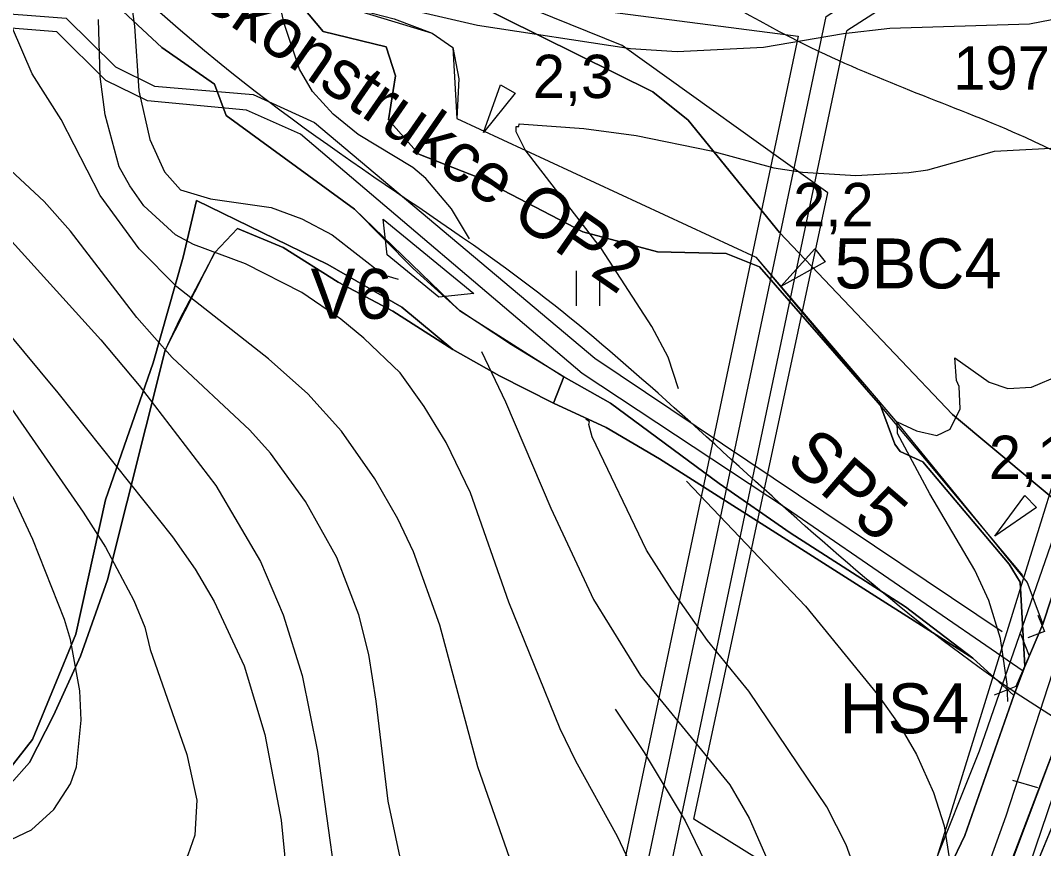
# Model space of a CAD drawing. Extents: x -684583 to -680383, y -1157874 to -1154904.
# Drawn here: x -683060.3 to -682753.2, y -1156107.3 to -1155858.8 of the extents above; entities that cross this region are included whole.
import ezdxf

# ---------------------------------------------------------------- set-up
doc = ezdxf.new("R2010")
doc.units = 0
for name, color, linetype in [('01_DOPRAVA', 7, 'Continuous'), ('01_PRVKY PSZ', 7, 'Continuous'), ('01_VRSTEVNICE', 7, 'Continuous'), ('02_KULTURY STAV', 7, 'Continuous'), ('03_PC_OBJEKTY_NÁVRH', 7, 'Continuous'), ('03_PC_OBJEKTY_STAV', 7, 'Continuous'), ('03_PC_STAV', 7, 'Continuous'), ('05_VHO_MELIORACE', 7, 'Continuous'), ('05_VHO_V_TOK', 7, 'Continuous'), ('06_BIOGEOGRAFIE', 7, 'Continuous'), ('06_ÚSES_IP', 7, 'Continuous'), ('07_ELEKTRO', 7, 'Continuous'), ('07_OCH_P A POPISY TI', 7, 'Continuous')]:
    doc.layers.add(name, color=color, linetype=linetype)

msp = doc.modelspace()

# ---------------------------------------------------------------- linework, layer by layer
at = {"layer": '01_DOPRAVA'}
msp.add_lwpolyline([(-682444.78, -1155001.44), (-682484.97, -1155081.41), (-682523.81, -1155212.27), (-682554.69, -1155333.36), (-682575.58, -1155465.36), (-682603.29, -1155587.36), (-682620.55, -1155650.97), (-682668.34, -1155796.22), (-682702.3, -1155906.34), (-682764.53, -1156097.63), (-682782.62, -1156147.93)], dxfattribs=at)
at = {"layer": '01_PRVKY PSZ'}
msp.add_lwpolyline([(-683103.66, -1155814.17), (-683023.93, -1155838.49), (-683005.49, -1155838.49), (-682978.82, -1155845.67), (-682966.79, -1155853.54), (-682936.74, -1155862.58), (-682930.53, -1155866.91), (-682929.33, -1155888.26), (-682839.59, -1155929.84), (-682759.46, -1156025.37)], dxfattribs=at)
at = {"layer": '01_VRSTEVNICE'}
for points in [[(-683028.81, -1155841.14), (-683026.1, -1155860.54), (-683024.81, -1155879.94), (-683021.53, -1155894.49), (-683017.11, -1155904.19), (-683012.26, -1155909.61), (-683003.28, -1155912.32), (-682985.02, -1155914.88), (-682975.89, -1155918.31), (-682966.76, -1155923.16), (-682951.35, -1155935.14), (-682946.93, -1155936.42)], [(-682925.53, -1155924.3), (-682930.95, -1155915.31), (-682938.66, -1155906.18), (-682942.51, -1155902.9), (-682958.91, -1155893.06), (-682966.47, -1155886.93), (-682972.61, -1155880.08), (-682976.6, -1155873.38), (-682981.17, -1155859.68), (-682982.45, -1155853.97), (-682981.88, -1155849.7), (-682977.03, -1155849.12), (-682969.04, -1155849.55), (-682923.11, -1155860.25), (-682877.18, -1155867.24), (-682863.2, -1155868.1), (-682837.24, -1155866.81), (-682813.27, -1155862.68), (-682799.29, -1155861.11), (-682757.36, -1155859.82), (-682741.38, -1155856.68)], [(-682903.85, -1156137.55), (-682922.97, -1156082.78), (-682934.38, -1156040.27), (-682942.37, -1156018.3), (-682947.07, -1156008.32), (-682953.92, -1155996.33), (-682963.91, -1155982.07), (-682974.03, -1155970.8), (-682985.87, -1155960.39), (-683013.4, -1155938.71), (-683024.67, -1155927.29), (-683036.37, -1155911.32), (-683048.07, -1155888.49), (-683056.77, -1155874.8), (-683062.76, -1155861.11)], [(-682864.48, -1156138.69), (-682881.03, -1156103.74), (-682893.58, -1156081.06), (-682898.29, -1156071.36), (-682913.69, -1156033.42), (-682925.25, -1156000.61), (-682932.52, -1155985.49), (-682939.08, -1155974.65), (-682946.36, -1155964.52), (-682957.2, -1155954.11), (-682964.19, -1155948.4), (-682975.89, -1155940.42), (-682992.72, -1155931.86), (-683008.41, -1155926.01), (-683013.83, -1155923.16), (-683023.24, -1155914.46), (-683027.52, -1155908.46), (-683030.66, -1155902.76), (-683034.94, -1155887.07), (-683036.37, -1155875.66), (-683036.94, -1155858.54)], [(-682862.77, -1155969.37), (-682865.91, -1155959.82), (-682870.76, -1155950.69), (-682885.88, -1155927.29), (-682908.84, -1155897.62), (-682911.55, -1155892.2), (-682911.55, -1155890.63), (-682910.7, -1155890.63), (-682910.56, -1155889.78), (-682891.16, -1155891.21), (-682875.47, -1155893.34), (-682852.93, -1155897.91), (-682834.1, -1155903.04), (-682825.54, -1155904.33), (-682809.56, -1155905.33), (-682793.59, -1155904.47), (-682787.88, -1155903.61), (-682767.91, -1155898.05), (-682739.67, -1155896.48), (-682729.97, -1155893.06), (-682722.12, -1155888.64), (-682713.42, -1155881.5), (-682708.82, -1155876.58), (-682703.58, -1155868.67)], [(-682946.36, -1156110.02), (-682949.93, -1156093.05), (-682953.49, -1156063.09), (-682955.77, -1156049.11), (-682958.77, -1156037.13), (-682965.33, -1156020.01), (-682974.75, -1156003.18), (-682985.3, -1155988.63), (-682991.43, -1155981.78), (-683014.83, -1155959.96), (-683025.38, -1155947.98), (-683045.35, -1155922.02), (-683053.2, -1155913.17), (-683076.45, -1155891.63)], [(-683067.75, -1155919.88), (-683036.22, -1155954.68), (-683024.67, -1155968.38), (-683001.7, -1155998.33), (-682988.3, -1156021.15), (-682981.45, -1156037.13), (-682975.74, -1156055.39), (-682971.18, -1156078.21), (-682965.76, -1156117.01), (-682963.33, -1156139.83), (-682962.76, -1156160.37), (-682964.05, -1156167.22), (-682966.47, -1156174.5), (-682969.33, -1156179.06), (-682973.03, -1156182.91), (-682977.17, -1156185.76), (-682981.45, -1156187.76), (-682991.58, -1156189.47), (-683046.07, -1156188.19), (-683064.04, -1156186.33)], [(-683080.59, -1155932.71), (-683049.06, -1155970.51), (-683014.69, -1156013.74), (-683007.84, -1156023.44), (-683002.13, -1156033.14), (-682993.15, -1156052.53), (-682987.01, -1156073.08), (-682982.02, -1156098.75), (-682981.02, -1156109.02), (-682981.45, -1156119.29), (-682983.16, -1156128.99), (-682984.87, -1156133.84), (-682987.58, -1156138.69), (-682999.28, -1156149.68), (-683012.97, -1156155.95), (-683024.1, -1156157.52), (-683035.23, -1156157.09), (-683066.89, -1156151.24)], [(-682763.92, -1156063.23), (-682764.06, -1156057.96), (-682766.06, -1156044.26), (-682769.62, -1156032.85), (-682773.76, -1156023.72), (-682787.31, -1156000.9), (-682797.01, -1155982.78), (-682797.15, -1155979.22), (-682791.31, -1155981.93), (-682785.17, -1155983.35), (-682781.18, -1155981.5), (-682778.18, -1155975.36), (-682778.47, -1155968.66), (-682779.32, -1155966.81), (-682779.85, -1155960.09), (-682769.48, -1155967.38), (-682763.92, -1155969.23), (-682756.79, -1155968.8), (-682748.23, -1155965.24), (-682741.09, -1155960.1), (-682731.82, -1155949.97), (-682724.12, -1155937.85), (-682722.55, -1155934.28)], [(-683077.45, -1155954.68), (-683041.5, -1156006.32), (-683034.8, -1156016.87), (-683026.24, -1156032.85), (-683022.96, -1156040.84), (-683021.39, -1156047.54), (-683010.41, -1156079.07), (-683007.41, -1156092.76), (-683007.98, -1156103.32), (-683010.12, -1156109.31), (-683015.26, -1156116.3), (-683018.68, -1156119.15), (-683030.66, -1156126.14), (-683042.65, -1156129.99), (-683054.63, -1156131.42), (-683087.43, -1156132.7)], [(-682921.93, -1155958.14), (-682914.69, -1155973.22), (-682901.14, -1156005.18), (-682888.3, -1156032.56), (-682874.18, -1156055.39), (-682847.36, -1156088.2), (-682841.52, -1156098.18), (-682835.53, -1156111.88)], [(-682808.28, -1156117.58), (-682812.42, -1156106.17), (-682818.27, -1156094.76), (-682841.66, -1156060.09), (-682854.07, -1156044.83), (-682864.77, -1156029.71), (-682872.33, -1156017.73), (-682888.73, -1155983.78), (-682889.73, -1155980.07), (-682889.45, -1155979.22), (-682890.59, -1155978.5)], [(-683065.18, -1156105.6), (-683057.05, -1156101.75), (-683050.35, -1156095.61), (-683045.35, -1156087.91), (-683043.5, -1156082.78), (-683042.07, -1156068.8), (-683042.5, -1156059.95), (-683045.35, -1156044.55), (-683047.07, -1156038.56), (-683056.62, -1156014.59), (-683064.04, -1155998.62)], [(-682860.35, -1155997.05), (-682824.68, -1156034.56), (-682803, -1156061.09), (-682796.3, -1156070.51), (-682791.31, -1156079.07), (-682786.17, -1156090.48), (-682783.03, -1156100.46), (-682781.32, -1156111.45)], [(-682881.82, -1156065.53), (-682873.04, -1156078.5), (-682860.77, -1156099.04), (-682854.78, -1156111.45), (-682849.5, -1156125.85), (-682847.08, -1156134.98), (-682844.23, -1156151.53), (-682837.38, -1156204.02), (-682836.95, -1156222.28), (-682839.66, -1156245.39), (-682843.66, -1156261.37), (-682847.36, -1156272.78), (-682851.36, -1156281.91), (-682859.06, -1156295.03), (-682870.76, -1156308.01)], [(-682754.93, -1156089.05), (-682762.35, -1156086.91)]]:
    msp.add_lwpolyline(points, dxfattribs=at)
at = {"layer": '02_KULTURY STAV'}
for points in [[(-682742.95, -1156008.33), (-682780.55, -1155977.07), (-682832.46, -1155922.39), (-682859.9, -1155888.72), (-682870.47, -1155880.23), (-682937.94, -1155846.74), (-682971.26, -1155836.19), (-683011.54, -1155826.68), (-683018.47, -1155820.23), (-683023.17, -1155813.67), (-683027.63, -1155799.73), (-683026.39, -1155782.8), (-683015.08, -1155760.81), (-683000.24, -1155747.04), (-682981.15, -1155735.79), (-682979.06, -1155725.2), (-682969.44, -1155700.39)], [(-682982.05, -1155846.95), (-682969.48, -1155862.12), (-682950.5, -1155866.7), (-682947.78, -1155875.42), (-682949.83, -1155888.58), (-682940.72, -1155898.9), (-682922.63, -1155905.99), (-682891.46, -1155922.2), (-682869.06, -1155928.21), (-682848.46, -1155928.75), (-682838.47, -1155932.76), (-682802.16, -1155974.34), (-682797.79, -1155985.99), (-682796.23, -1155988.19), (-682789.4, -1155991.25), (-682763.46, -1156021.97), (-682760.21, -1156027.41), (-682758.74, -1156052.65), (-682762.11, -1156061.38), (-682774.36, -1156050.2), (-682794.57, -1156034.77), (-682829.27, -1156012.57), (-682850.55, -1155997.73), (-682883.15, -1155973.67), (-682897.2, -1155965.7), (-682912.92, -1155956.13), (-682928.48, -1155945.79), (-682942.41, -1155933.25), (-682960.08, -1155915.44), (-682998.59, -1155887.31), (-683002.04, -1155877.92), (-683017.87, -1155866.9), (-683035.29, -1155850.57)], [(-682937.94, -1155846.74), (-682870.47, -1155880.23), (-682859.9, -1155888.72), (-682832.46, -1155922.39), (-682780.55, -1155977.07), (-682742.95, -1156008.33), (-682753.41, -1156039.97), (-682758.74, -1156052.65), (-682760.21, -1156027.41), (-682763.46, -1156021.97), (-682789.4, -1155991.25), (-682796.23, -1155988.19), (-682797.79, -1155985.99), (-682802.16, -1155974.34), (-682838.47, -1155932.76), (-682848.46, -1155928.75), (-682869.06, -1155928.21), (-682891.46, -1155922.2), (-682922.63, -1155905.99), (-682940.72, -1155898.9), (-682949.83, -1155888.58), (-682947.78, -1155875.42), (-682950.5, -1155866.7), (-682969.48, -1155862.12), (-682982.05, -1155846.95)], [(-683035.29, -1155850.57), (-683017.87, -1155866.9), (-683002.04, -1155877.92), (-682998.59, -1155887.31), (-682960.08, -1155915.44), (-682928.48, -1155945.79), (-682897.2, -1155965.7), (-682900.29, -1155973.66), (-682916.5, -1155965.49), (-682930.5, -1155957.52), (-682945.8, -1155944.83), (-682968.02, -1155932.05), (-683007.47, -1155912.82), (-683011.52, -1155929.88), (-683020.52, -1155961.53), (-683034.76, -1156002.64), (-683043.66, -1156042.98), (-683056.67, -1156074.55), (-683074.73, -1156097.48)], [(-683074.73, -1156097.48), (-683056.67, -1156074.55), (-683043.66, -1156042.98), (-683034.76, -1156002.64), (-683020.52, -1155961.53), (-683011.52, -1155929.88), (-683007.47, -1155912.82), (-682968.02, -1155932.05), (-682945.8, -1155944.83), (-682930.5, -1155957.52), (-682948.54, -1155946.03), (-682964.91, -1155937.3), (-682981.45, -1155926.93), (-682995.17, -1155921.22), (-683001.94, -1155928.39), (-683012.54, -1155948.51), (-683016.88, -1155957.76), (-683034.2, -1156026.69), (-683042.27, -1156049.61), (-683050.39, -1156067.39), (-683057.59, -1156081.49), (-683063.12, -1156087.72)], [(-683063.12, -1156087.72), (-683057.59, -1156081.49), (-683050.39, -1156067.39), (-683042.27, -1156049.61), (-683034.2, -1156026.69), (-683016.88, -1155957.76), (-683001.94, -1155928.39), (-682995.17, -1155921.22), (-682981.45, -1155926.93), (-682964.91, -1155937.3), (-682948.54, -1155946.03), (-682930.5, -1155957.52), (-682916.5, -1155965.49), (-682900.29, -1155973.66), (-682884.48, -1155980.97), (-682868.52, -1155990.38), (-682774.36, -1156050.2), (-682762.11, -1156061.38), (-682776.79, -1156103.44), (-682785.78, -1156122.22)], [(-682893.49, -1155933.91), (-682893.49, -1155944.41)], [(-682886.49, -1155933.91), (-682886.49, -1155944.41)], [(-682866.04, -1156320.76), (-682848.78, -1156285.62), (-682834.97, -1156248.66), (-682815.59, -1156196.79), (-682810.04, -1156179.89), (-682785.78, -1156122.22), (-682776.79, -1156103.44), (-682762.11, -1156061.38), (-682758.74, -1156052.65), (-682753.41, -1156039.97), (-682742.95, -1156008.33), (-682725.67, -1156001.43), (-682739.11, -1156046.65), (-682740.04, -1156050.18), (-682744.64, -1156063.3), (-682765.72, -1156119.15), (-682779.93, -1156155.81), (-682782.44, -1156169.94), (-682798.74, -1156209.36), (-682837.34, -1156293.13), (-682860.97, -1156340.11)], [(-682596.72, -1156380.07), (-682557.32, -1156288.22), (-682537.57, -1156239.43), (-682529.35, -1156221.47), (-682529.35, -1156221.47), (-682525.25, -1156214.91), (-682536.68, -1156197.77), (-682569.3, -1156156.35), (-682580.04, -1156146.44), (-682601.47, -1156130.49), (-682624.62, -1156116.74), (-682638.27, -1156107.54), (-682659.05, -1156095.72), (-682693.74, -1156078.06), (-682714.33, -1156069.98), (-682731.17, -1156065.1), (-682740.76, -1156063.41), (-682744.64, -1156063.3), (-682779.93, -1156155.81), (-682782.44, -1156169.94), (-682798.74, -1156209.36), (-682837.34, -1156293.13), (-682860.97, -1156340.11)]]:
    msp.add_lwpolyline(points, dxfattribs=at)
msp.add_lwpolyline([(-682897.2, -1155965.7), (-682883.15, -1155973.67), (-682850.55, -1155997.73), (-682829.27, -1156012.57), (-682794.57, -1156034.77), (-682774.36, -1156050.2), (-682868.52, -1155990.38), (-682884.48, -1155980.97), (-682900.29, -1155973.66)], close=True, dxfattribs=at)
at = {"layer": '03_PC_OBJEKTY_NÁVRH'}
msp.add_lwpolyline([(-683162.95, -1155912.75), (-683145.43, -1155885.76), (-683118.84, -1155861.84), (-683102.86, -1155853.78), (-683046.59, -1155858.08), (-683031.82, -1155872.72), (-683020.13, -1155878.5), (-682990.45, -1155881.05), (-682972.06, -1155889.38), (-682887.85, -1155960.19), (-682765.64, -1156042.16)], dxfattribs=at)
msp.add_lwpolyline([(-682924.18, -1155940.78), (-682934.73, -1155941.83), (-682950.2, -1155929.15), (-682951.45, -1155918.43)], close=True, dxfattribs=at)
at = {"layer": '03_PC_OBJEKTY_STAV'}
for points in [[(-682754.88, -1156037.24), (-682752.93, -1156042.17), (-682757.87, -1156044.12)], [(-682760.11, -1156042.89), (-682757.49, -1156049.46), (-682761.44, -1156058.64), (-682768.01, -1156061.26)]]:
    msp.add_lwpolyline(points, dxfattribs=at)
at = {"layer": '03_PC_STAV'}
msp.add_lwpolyline([(-682759.31, -1156054.08), (-682830.38, -1156005.24), (-682891.64, -1155964.72), (-682976.25, -1155892.91), (-682992.49, -1155885.69), (-683022.17, -1155882.95), (-683034.72, -1155876.81), (-683049.43, -1155862.22), (-683077.1, -1155860.02)], dxfattribs=at)
at = {"layer": '05_VHO_MELIORACE'}
msp.add_line((-682772.31, -1156153.49), (-682747.8, -1156093.97), dxfattribs=at)
msp.add_lwpolyline([(-682427.32, -1155652.04), (-682442.64, -1155733.79), (-682379.89, -1155766.86), (-682399.94, -1155848.22), (-682465.23, -1155827.02), (-682513.91, -1155819), (-682556.29, -1155928.43), (-682568.9, -1156017.02), (-682570.04, -1156062.28), (-682551.72, -1156093.79), (-682504.18, -1156161.97), (-682541.38, -1156231.07), (-682567.04, -1156285.02), (-682772.31, -1156153.49), (-682747.8, -1156093.97), (-682704.39, -1155977.74), (-682664.8, -1155838.52), (-682635.04, -1155749.47), (-682580.41, -1155551.03)], dxfattribs=at)
msp.add_lwpolyline([(-683016.49, -1155781.73), (-682936.04, -1155794.17), (-682848.83, -1155761.96), (-682691.86, -1155808.93), (-682793.99, -1156138.37), (-682858.18, -1156098.46), (-682817.93, -1155910.57), (-682879.64, -1155866.28), (-683019.17, -1155809.91)], close=True, dxfattribs=at)
at = {"layer": '05_VHO_V_TOK'}
msp.add_lwpolyline([(-683023.93, -1155838.49), (-683011.69, -1155835.91), (-682997.73, -1155839.11), (-682978.82, -1155845.67), (-682966.79, -1155853.54), (-682948.1, -1155858.31), (-682936.74, -1155862.58), (-682930.53, -1155866.91), (-682928.72, -1155876.3), (-682929.33, -1155888.26), (-682839.59, -1155929.84), (-682797.61, -1155978.91), (-682758.08, -1156027.46), (-682753.41, -1156039.97)], dxfattribs=at)
for points in [[(-682916.19, -1155878.15), (-682911.83, -1155880.59), (-682921.34, -1155892.46)], [(-682821.83, -1155927.35), (-682818.74, -1155931.28), (-682832.07, -1155938.6)], [(-682758.74, -1156001.38), (-682755.28, -1156004.98), (-682767.82, -1156013.58)]]:
    msp.add_lwpolyline(points, close=True, dxfattribs=at)
at = {"layer": '06_BIOGEOGRAFIE'}
for points in [[(-682624.87, -1154935.44), (-682669.05, -1155140.04), (-682739.65, -1155253.72), (-682834.36, -1155382.91), (-682941.12, -1155661.96), (-683008.28, -1155760.14), (-683056.49, -1155810.09), (-683084.04, -1155808.37), (-683154.45, -1155886.49), (-683231.94, -1156062.19), (-683280.08, -1156211.64), (-683362.74, -1156430.39), (-683497.05, -1156731.83), (-683541.82, -1156781.78), (-683638.25, -1156792.12), (-683701.96, -1156768), (-683817.33, -1156693.94)], [(-682538.3, -1156231.46), (-682619.23, -1156136.72), (-682741.49, -1156072.99), (-682905.07, -1155940.36), (-683017, -1155857.68), (-683037.66, -1155826.67), (-683017, -1155811.17), (-682820.7, -1155868.01), (-682758.71, -1155893.85), (-682674.33, -1155943.8), (-682548.63, -1156054.04), (-682459.09, -1156176.34)]]:
    msp.add_spline(points, degree=3, dxfattribs=at)
at = {"layer": '06_ÚSES_IP'}
for points in [[(-682530.18, -1155187.74), (-682556.31, -1155287.32), (-682580.65, -1155417.4), (-682596.62, -1155505.37), (-682619.02, -1155596.96), (-682637.3, -1155662.36), (-682672.55, -1155772.07), (-682712.43, -1155905.02), (-682772.45, -1156078.06), (-682846.1, -1156262.2), (-682899.06, -1156383.28), (-682928.82, -1156472.07), (-682968.71, -1156622.54), (-683017.6, -1156838.34)], [(-683045.5, -1156945.1), (-682993.87, -1156850.83), (-682970.35, -1156763.63), (-682943.14, -1156635.49), (-682907.69, -1156485.87), (-682877.43, -1156403.71), (-682855.81, -1156343.74), (-682797.01, -1156219.49), (-682773.09, -1156158.67), (-682722.07, -1156008.47), (-682663.84, -1155833.77), (-682598.99, -1155629.09), (-682554.6, -1155429.31), (-682533.56, -1155299)]]:
    msp.add_lwpolyline(points, dxfattribs=at)
at = {"layer": '07_ELEKTRO'}
msp.add_lwpolyline([(-683353.35, -1157770.3), (-683109.07, -1157109.08), (-683073.5, -1157019.42), (-683054.68, -1156978.22), (-683011.49, -1156911.63), (-683020.57, -1156816.29), (-682818.44, -1155857.57), (-682314.17, -1155533.82)], dxfattribs=at)
msp.add_lwpolyline([(-683353.35, -1157770.3), (-683109.07, -1157109.08), (-683073.5, -1157019.42), (-683054.68, -1156978.22), (-683011.49, -1156911.63), (-683020.57, -1156816.29), (-682818.44, -1155857.57), (-682314.17, -1155533.82)], dxfattribs=at)
at = {"layer": '07_OCH_P A POPISY TI'}
for p, q in [((-682310.39, -1155539.71), (-682812.19, -1155861.88)), ((-683092.19, -1155828.75), (-682826.85, -1155863.53)), ((-682826.85, -1155863.53), (-683027.64, -1156815.89)), ((-683013.5, -1156816.69), (-682812.19, -1155861.88))]:
    msp.add_line(p, q, dxfattribs=at)

# ---------------------------------------------------------------- texts
at = {"layer": '01_PRVKY PSZ'}
msp.add_text('rekonstrukce OP2', height=15, rotation=325.3153, dxfattribs=at).set_placement((-683012.55, -1155849.91))
at = {"layer": '03_PC_OBJEKTY_NÁVRH'}
msp.add_text('V6', height=15, dxfattribs=at).set_placement((-682973.19, -1155948.33))
msp.add_text('SP5', height=15, rotation=319.3016, dxfattribs=at).set_placement((-682831.09, -1155991.32))
at = {"layer": '03_PC_OBJEKTY_STAV'}
msp.add_text('HS4', height=15, dxfattribs=at).set_placement((-682814.46, -1156072.74))
at = {"layer": '05_VHO_MELIORACE'}
msp.add_text('1970', height=13, dxfattribs=at).set_placement((-682780.26, -1155879.54))
at = {"layer": '05_VHO_V_TOK'}
for s, p in [('2,3', (-682906.53, -1155882.08)), ('2,2', (-682828.34, -1155920.56)), ('2,1', (-682769.59, -1155996.4))]:
    msp.add_text(s, height=13, dxfattribs=at).set_placement(p)
at = {"layer": '06_BIOGEOGRAFIE'}
msp.add_text('5BC4', height=15, dxfattribs=at).set_placement((-682815.95, -1155939.22))

doc.saveas('drawing.dxf')
